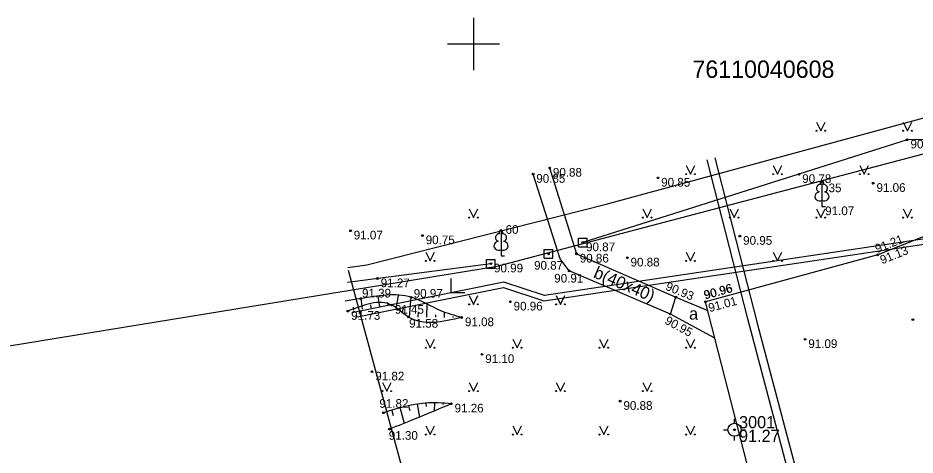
# Model space of a CAD drawing. Extents: x 634272 to 634544, y 247463 to 247653.
# Drawn here: x 634323.8 to 634375.4, y 247576.3 to 247601.5 of the extents above; entities that cross this region are included whole.
import ezdxf

# ---------------------------------------------------------------- set-up
doc = ezdxf.new("R2010")
doc.units = 0
for name, color, linetype in [('CELI_CAPM_####_####_#', 7, 'Continuous'), ('CELI_CMAL_####_####_#', 7, 'Continuous'), ('CELI_CSEG_####_TKST_#', 7, 'Continuous'), ('CELI_SEGL_####_####_#', 7, 'Continuous'), ('ELEK_VADP_ZSPR_####_#', 7, 'Continuous'), ('GEOD_ELEM_####_####_#', 7, 'Continuous'), ('GEOD_ELEM_####_TKST_#', 7, 'Continuous'), ('NORB_ELEM_####_####_#', 7, 'Continuous'), ('NORB_ZOGS_SBST_####_#', 7, 'Continuous'), ('RAMI_UZMR_####_####_#', 7, 'Continuous'), ('RELJ_AATZ_####_TKST_#', 7, 'Continuous'), ('RELJ_ELEM_####_####_#', 7, 'Continuous'), ('RELJ_NOGA_####_####_#', 7, 'Continuous'), ('RELJ_NOGL_####_####_#', 7, 'Continuous'), ('ROBZ_KADS_####_TKST_#', 7, 'Continuous'), ('ROBZ_UZMR_####_####_#', 7, 'Continuous'), ('SILT_VADP_UDEN_####_#', 7, 'Continuous'), ('TERT_DIAM_####_TKST_#', 7, 'Continuous'), ('TERT_ELEM_####_####_#', 7, 'Continuous')]:
    doc.layers.add(name, color=color, linetype=linetype)

msp = doc.modelspace()

# ---------------------------------------------------------------- linework, layer by layer
at = {"layer": 'CELI_CAPM_####_####_#'}
for points in [[(634380.824, 247590.847), (634373.276, 247587.854), (634363.359, 247585.148)], [(634368.714, 247564.266), (634363.359, 247585.148)]]:
    msp.add_lwpolyline(points, dxfattribs=at)
at = {"layer": 'CELI_CMAL_####_####_#'}
for points in [[(634363.899, 247583.043), (634361.334, 247584.443), (634355.51, 247586.928), (634354.985, 247587.627), (634353.424, 247592.504)], [(634354.379, 247592.858), (634355.928, 247587.908), (634361.654, 247585.412), (634363.488, 247584.647)]]:
    msp.add_lwpolyline(points, dxfattribs=at)
at = {"layer": 'CELI_SEGL_####_####_#'}
msp.add_lwpolyline([(634361.334, 247584.443), (634361.654, 247585.412)], dxfattribs=at)
at = {"layer": 'ELEK_VADP_ZSPR_####_#'}
for points in [[(634392.231, 247587.355), (634392.234, 247587.84), (634386.266, 247591.23), (634380.125, 247589.395), (634354.078, 247585.508), (634351.746, 247586.285), (634342.99, 247584.518)], [(634343.193, 247584.255), (634351.727, 247585.977), (634354.051, 247585.199), (634380.191, 247589.102), (634385.926, 247590.879), (634391.152, 247588.32), (634392.016, 247587.645), (634392.036, 247587.305)]]:
    msp.add_lwpolyline(points, dxfattribs=at)
at = {"layer": 'GEOD_ELEM_####_####_#'}
for p, q in [((634350, 247601.5), (634350, 247600)), ((634348.5, 247600), (634350, 247600)), ((634350, 247600), (634350, 247598.5)), ((634350, 247600), (634351.5, 247600)), ((634365.028, 247578.149), (634365.028, 247578.399)), ((634364.403, 247577.774), (634364.653, 247577.774)), ((634365.028, 247577.149), (634365.028, 247577.399)), ((634365.403, 247577.774), (634365.653, 247577.774))]:
    msp.add_line(p, q, dxfattribs=at)
for radius in [0.375, 0.05]:
    msp.add_circle((634365.028, 247577.774), radius, dxfattribs=at)
at = {"layer": 'NORB_ELEM_####_####_#'}
for p, q in [((634356.041, 247588.311), (634356.041, 247588.811)), ((634356.041, 247588.811), (634356.541, 247588.811)), ((634356.541, 247588.311), (634356.541, 247588.811)), ((634356.041, 247588.311), (634356.541, 247588.311)), ((634354.071, 247587.655), (634354.071, 247588.155)), ((634354.071, 247588.155), (634354.571, 247588.155)), ((634354.571, 247587.655), (634354.571, 247588.155)), ((634350.741, 247587.091), (634350.741, 247587.591)), ((634350.741, 247587.591), (634351.241, 247587.591)), ((634351.241, 247587.091), (634351.241, 247587.591)), ((634354.071, 247587.655), (634354.571, 247587.655)), ((634350.741, 247587.091), (634351.241, 247587.091))]:
    msp.add_line(p, q, dxfattribs=at)
for centre in [(634356.291, 247588.561), (634354.321, 247587.905), (634350.991, 247587.341)]:
    msp.add_circle(centre, 0.0504, dxfattribs=at)
at = {"layer": 'NORB_ZOGS_SBST_####_#'}
for points in [[(634378.177, 247594.542), (634374.98, 247594.484), (634368.742, 247592.493), (634356.291, 247588.561)], [(634350.991, 247587.341), (634342.738, 247586.262)]]:
    msp.add_lwpolyline(points, dxfattribs=at)
at = {"layer": 'RAMI_UZMR_####_####_#'}
for points in [[(634342.761, 247587.127), (634343.841, 247587.277), (634357.63, 247590.775), (634379.264, 247596.642)], [(634376.048, 247532.596), (634371.988, 247530.992), (634368.176, 247529.515), (634358.81, 247527.799), (634352.082, 247552.749), (634342.787, 247586.946)]]:
    msp.add_lwpolyline(points, dxfattribs=at)
at = {"layer": 'RELJ_ELEM_####_####_#'}
for centre in [(634374.98, 247594.484), (634354.379, 247592.858), (634353.424, 247592.504), (634368.742, 247592.493), (634360.618, 247592.284), (634373.021, 247591.979), (634342.91, 247589.239), (634347.055, 247588.964), (634365.34, 247588.932), (634356.291, 247588.561), (634354.321, 247587.905), (634355.928, 247587.908), (634358.853, 247587.683), (634373.276, 247587.854), (634350.991, 247587.341), (634355.51, 247586.928), (634344.464, 247586.488), (634343.497, 247585.333), (634346.406, 247585.406), (634352.117, 247585.148), (634361.654, 247585.412), (634363.359, 247585.148), (634342.76, 247584.609), (634345.28, 247584.959), (634346.238, 247584.271), (634349.314, 247584.242), (634361.334, 247584.443), (634375.302, 247584.119), (634369.094, 247582.985), (634350.483, 247582.118), (634344.149, 247581.117), (634358.445, 247579.422), (634348.717, 247579.273), (634344.807, 247578.754), (634345.151, 247577.811)]:
    msp.add_circle(centre, 0.05, dxfattribs=at)
at = {"layer": 'RELJ_NOGA_####_####_#'}
for p, q in [((634343.601, 247584.726), (634343.516, 247585.336)), ((634344.592, 247584.863), (634344.507, 247585.475)), ((634345.558, 247584.859), (634345.666, 247585.51)), ((634346.314, 247584.27), (634346.406, 247585.406)), ((634343.106, 247584.657), (634343.081, 247584.836)), ((634344.096, 247584.795), (634344.071, 247584.98)), ((634345.087, 247584.932), (634345.063, 247585.107)), ((634345.885, 247584.482), (634345.955, 247584.776)), ((634347.314, 247584.261), (634347.321, 247585.008)), ((634346.814, 247584.266), (634346.817, 247584.565)), ((634347.814, 247584.256), (634347.815, 247584.404)), ((634348.314, 247584.251), (634348.317, 247584.567)), ((634348.814, 247584.247), (634348.814, 247584.294)), ((634349.314, 247584.242), (634349.314, 247584.243)), ((634345.774, 247579.007), (634346.008, 247578.149)), ((634346.258, 247579.134), (634346.317, 247578.891)), ((634346.747, 247579.24), (634346.882, 247578.502)), ((634347.241, 247579.311), (634347.259, 247579.12)), ((634347.741, 247579.323), (634347.729, 247578.856)), ((634348.24, 247579.297), (634348.236, 247579.228)), ((634344.807, 247578.754), (634344.807, 247578.753)), ((634345.292, 247578.876), (634345.365, 247578.602))]:
    msp.add_line(p, q, dxfattribs=at)
for points in [[(634349.314, 247584.242), (634346.238, 247584.271), (634345.28, 247584.959), (634342.76, 247584.609)], [(634348.717, 247579.273), (634347.213, 247579.308), (634344.807, 247578.754)]]:
    msp.add_spline(points, degree=3, dxfattribs=at)
at = {"layer": 'RELJ_NOGL_####_####_#'}
for points in [[(634349.314, 247584.242), (634348.107, 247584.635), (634346.406, 247585.406), (634343.497, 247585.333), (634342.598, 247585.184)], [(634348.717, 247579.273), (634346.628, 247578.398), (634345.151, 247577.811)]]:
    msp.add_spline(points, degree=3, dxfattribs=at)
at = {"layer": 'ROBZ_UZMR_####_####_#'}
for points in [[(634351.357, 247587.202), (634377.661, 247594.14)], [(634294.168, 247577.875), (634351.357, 247587.202)]]:
    msp.add_lwpolyline(points, dxfattribs=at)
at = {"layer": 'SILT_VADP_UDEN_####_#'}
for points in [[(634363.886, 247593.437), (634366.36, 247583.831), (634369.421, 247572.245), (634372.593, 247560.517), (634376.47, 247547.723), (634378.808, 247540.177), (634380.88, 247533.487)], [(634380.38, 247533.332), (634378.785, 247538.524), (634375.914, 247547.864), (634373.98, 247554.308), (634372.046, 247560.751), (634368.919, 247572.314), (634365.801, 247584.167), (634363.457, 247593.328)]]:
    msp.add_lwpolyline(points, dxfattribs=at)
at = {"layer": 'TERT_ELEM_####_####_#'}
for p, q in [((634369.75, 247595.5), (634370, 247595)), ((634370, 247595), (634370.25, 247595.5)), ((634374.75, 247595.5), (634375, 247595)), ((634375, 247595), (634375.25, 247595.5)), ((634362.25, 247593), (634362.5, 247592.5)), ((634362.5, 247592.5), (634362.75, 247593)), ((634367.25, 247593), (634367.5, 247592.5)), ((634367.5, 247592.5), (634367.75, 247593)), ((634372.25, 247593), (634372.5, 247592.5)), ((634372.5, 247592.5), (634372.75, 247593)), ((634370.065, 247590.986), (634370.065, 247590.639)), ((634349.75, 247590.5), (634350, 247590)), ((634350, 247590), (634350.25, 247590.5)), ((634359.75, 247590.5), (634360, 247590)), ((634360, 247590), (634360.25, 247590.5)), ((634364.75, 247590.5), (634365, 247590)), ((634365, 247590), (634365.25, 247590.5)), ((634369.75, 247590.5), (634370, 247590)), ((634370, 247590), (634370.25, 247590.5)), ((634370.065, 247590.639), (634370.265, 247590.639)), ((634374.75, 247590.5), (634375, 247590)), ((634375, 247590), (634375.25, 247590.5)), ((634347.25, 247588), (634347.5, 247587.5)), ((634347.5, 247587.5), (634347.75, 247588)), ((634351.579, 247588.144), (634351.579, 247587.797)), ((634351.579, 247587.797), (634351.779, 247587.797)), ((634362.25, 247588), (634362.5, 247587.5)), ((634362.5, 247587.5), (634362.75, 247588)), ((634367.25, 247588), (634367.5, 247587.5)), ((634367.5, 247587.5), (634367.75, 247588)), ((634348.694, 247586.491), (634348.694, 247585.691)), ((634348.694, 247585.691), (634349.494, 247585.691)), ((634349.75, 247585.5), (634350, 247585)), ((634350, 247585), (634350.25, 247585.5)), ((634354.75, 247585.5), (634355, 247585)), ((634355, 247585), (634355.25, 247585.5)), ((634347.25, 247583), (634347.5, 247582.5)), ((634347.5, 247582.5), (634347.75, 247583)), ((634352.25, 247583), (634352.5, 247582.5)), ((634352.5, 247582.5), (634352.75, 247583)), ((634357.25, 247583), (634357.5, 247582.5)), ((634357.5, 247582.5), (634357.75, 247583)), ((634362.25, 247583), (634362.5, 247582.5)), ((634362.5, 247582.5), (634362.75, 247583)), ((634344.75, 247580.5), (634345, 247580)), ((634345, 247580), (634345.25, 247580.5)), ((634349.75, 247580.5), (634350, 247580)), ((634350, 247580), (634350.25, 247580.5)), ((634354.75, 247580.5), (634355, 247580)), ((634355, 247580), (634355.25, 247580.5)), ((634359.75, 247580.5), (634360, 247580)), ((634360, 247580), (634360.25, 247580.5)), ((634347.25, 247578), (634347.5, 247577.5)), ((634347.5, 247577.5), (634347.75, 247578)), ((634352.25, 247578), (634352.5, 247577.5)), ((634352.5, 247577.5), (634352.75, 247578)), ((634357.25, 247578), (634357.5, 247577.5)), ((634357.5, 247577.5), (634357.75, 247578)), ((634362.25, 247578), (634362.5, 247577.5)), ((634362.5, 247577.5), (634362.75, 247578))]:
    msp.add_line(p, q, dxfattribs=at)
for points in [[(634370.065, 247592.139), (634370.065, 247590.986)], [(634370.155, 247591.907), (634370.154, 247591.908)], [(634351.579, 247589.297), (634351.579, 247588.144)], [(634351.669, 247589.065), (634351.668, 247589.066)]]:
    msp.add_lwpolyline(points, dxfattribs=at)
for centre, radius in [((634369.75, 247595), 0.028), ((634370.25, 247595), 0.0263), ((634374.75, 247595), 0.028), ((634375.25, 247595), 0.0263), ((634362.25, 247592.5), 0.028), ((634362.75, 247592.5), 0.0263), ((634367.25, 247592.5), 0.028), ((634367.75, 247592.5), 0.0263), ((634372.25, 247592.5), 0.028), ((634372.75, 247592.5), 0.0263), ((634349.75, 247590), 0.028), ((634350.25, 247590), 0.0263), ((634359.75, 247590), 0.028), ((634360.25, 247590), 0.0263), ((634364.75, 247590), 0.028), ((634365.25, 247590), 0.0263), ((634369.75, 247590), 0.028), ((634370.25, 247590), 0.0263), ((634374.75, 247590), 0.028), ((634375.25, 247590), 0.0263), ((634347.25, 247587.5), 0.028), ((634347.75, 247587.5), 0.0263), ((634362.25, 247587.5), 0.028), ((634362.75, 247587.5), 0.0263), ((634367.25, 247587.5), 0.028), ((634367.75, 247587.5), 0.0263), ((634349.75, 247585), 0.028), ((634350.25, 247585), 0.0263), ((634354.75, 247585), 0.028), ((634355.25, 247585), 0.0263), ((634347.25, 247582.5), 0.028), ((634347.75, 247582.5), 0.0263), ((634352.25, 247582.5), 0.028), ((634352.75, 247582.5), 0.0263), ((634357.25, 247582.5), 0.028), ((634357.75, 247582.5), 0.0263), ((634362.25, 247582.5), 0.028), ((634362.75, 247582.5), 0.0263), ((634344.75, 247580), 0.028), ((634345.25, 247580), 0.0263), ((634349.75, 247580), 0.028), ((634350.25, 247580), 0.0263), ((634354.75, 247580), 0.028), ((634355.25, 247580), 0.0263), ((634359.75, 247580), 0.028), ((634360.25, 247580), 0.0263), ((634347.25, 247577.5), 0.028), ((634347.75, 247577.5), 0.0263), ((634352.25, 247577.5), 0.028), ((634352.75, 247577.5), 0.0263), ((634357.25, 247577.5), 0.028), ((634357.75, 247577.5), 0.0263), ((634362.25, 247577.5), 0.028), ((634362.75, 247577.5), 0.0263)]:
    msp.add_circle(centre, radius, dxfattribs=at)
for centre, major_axis, ratio, start_param, end_param in [((634369.937, 247591.694), (-0.039, -0.212), 0.861323, 3.141593, 6.283185), ((634370.065, 247591.989), (0, -0.15), 0.707107, 3.14537, 5.287485), ((634370.065, 247591.989), (0, -0.15), 0.707107, 0.995701, 3.137816), ((634370.193, 247591.694), (0.039, -0.212), 0.861323, 0, 3.141593), ((634369.975, 247591.232), (0.307, 0.095), 0.814445, 1.570796, 4.752015), ((634370.155, 247591.232), (-0.307, 0.095), 0.814445, 1.531171, 4.712389), ((634351.579, 247589.147), (0, -0.15), 0.707107, 3.14537, 5.287485), ((634351.579, 247589.147), (0, -0.15), 0.707107, 0.995701, 3.137816), ((634351.451, 247588.852), (-0.039, -0.212), 0.861323, 3.141593, 6.283185), ((634351.707, 247588.852), (0.039, -0.212), 0.861323, 0, 3.141593), ((634351.489, 247588.39), (0.307, 0.095), 0.814445, 1.570796, 4.752015), ((634351.669, 247588.39), (-0.307, 0.095), 0.814445, 1.531171, 4.712389)]:
    msp.add_ellipse(centre, major_axis=major_axis, ratio=ratio, start_param=start_param, end_param=end_param, dxfattribs=at)

# ---------------------------------------------------------------- texts
at = {"layer": 'CELI_CSEG_####_TKST_#'}
msp.add_text('b(40x40)', height=0.7, rotation=336.8929, dxfattribs=at).set_placement((634356.856, 247586.572))
msp.add_text('a', height=0.7, dxfattribs=at).set_placement((634362.411, 247584.117))
at = {"layer": 'GEOD_ELEM_####_TKST_#'}
for s, p in [(' 3001', (634365.028, 247577.863)), (' 91.27', (634365.028, 247577.074))]:
    msp.add_text(s, height=0.7, dxfattribs=at).set_placement(p)
at = {"layer": 'RELJ_AATZ_####_TKST_#'}
for s, p in [(' 90.88', (634374.98, 247593.984)), (' 90.85', (634353.424, 247592.004)), (' 90.88', (634354.379, 247592.358)), (' 90.78', (634368.742, 247591.993)), (' 90.85', (634360.618, 247591.784)), (' 91.06', (634373.021, 247591.479)), (' 91.07', (634370.065, 247590.139)), (' 91.07', (634342.91, 247588.739)), (' 90.75', (634347.055, 247588.464)), (' 90.95', (634365.34, 247588.432)), (' 90.87', (634356.291, 247588.061)), (' 90.86', (634355.928, 247587.408)), (' 90.99', (634350.991, 247586.841)), (' 90.87', (634353.297, 247586.997)), (' 90.88', (634358.853, 247587.183)), (' 90.91', (634354.458, 247586.253)), (' 91.27', (634344.464, 247585.988)), (' 91.39', (634343.385, 247585.395)), (' 90.97', (634346.364, 247585.383)), (' 90.96', (634352.117, 247584.648)), (' 91.45', (634345.28, 247584.459)), (' 91.73', (634342.76, 247584.109)), (' 91.58', (634346.098, 247583.656)), (' 91.08', (634349.314, 247583.742)), (' 91.09', (634369.094, 247582.485)), (' 91.10', (634350.483, 247581.618)), (' 91.82', (634344.149, 247580.617)), (' 91.82', (634344.386, 247579.04)), (' 91.26', (634348.717, 247578.773)), (' 90.88', (634358.445, 247578.922)), (' 91.30', (634344.927, 247577.199))]:
    msp.add_text(s, height=0.5, dxfattribs=at).set_placement(p)
for s, rotation, p in [(' 91.21', 21.6298, (634373.07, 247587.879)), (' 91.13', 21.6298, (634373.359, 247587.237)), (' 90.93', 337.3462, (634360.841, 247585.924)), (' 90.96', 15.2625, (634363.149, 247585.223)), (' 90.96', 15.2625, (634363.169, 247585.241)), (' 91.01', 15.2625, (634363.418, 247584.496)), (' 90.95', 331.3691, (634360.807, 247584.004))]:
    msp.add_text(s, height=0.5, rotation=rotation, dxfattribs=at).set_placement(p)
at = {"layer": 'ROBZ_KADS_####_TKST_#'}
msp.add_text('76110040608', height=1, dxfattribs=at).set_placement((634362.603, 247598.048))
at = {"layer": 'TERT_DIAM_####_TKST_#'}
for s, p in [('35', (634370.446, 247591.46)), ('60', (634351.841, 247589.062))]:
    msp.add_text(s, height=0.5, dxfattribs=at).set_placement(p)

doc.saveas('drawing.dxf')
